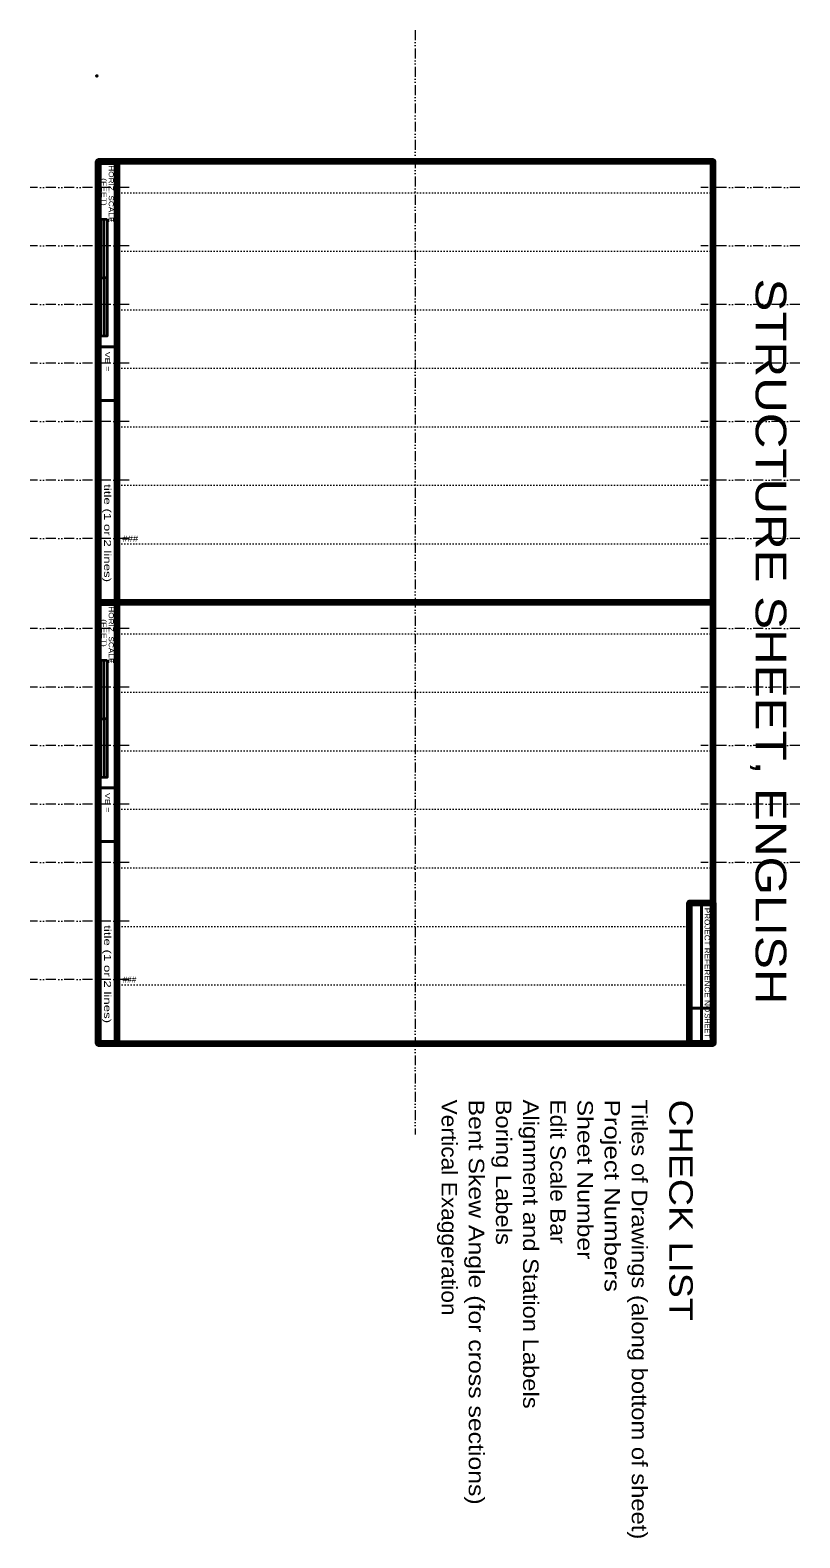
# Model space of a CAD drawing. Extents: x 278712 to 279914, y 171254 to 171792.
# Drawn here: x 279271.5 to 279402.9, y 171276.1 to 171533.7 of the extents above; entities that cross this region are included whole.
import ezdxf
from ezdxf.enums import TextEntityAlignment as Align

# ---------------------------------------------------------------- set-up
doc = ezdxf.new("R2010")
doc.units = 0
doc.header["$LTSCALE"] = 0.34
doc.header["$PDMODE"] = 32
doc.header["$PDSIZE"] = 0.17
doc.linetypes.add('DASH_DOUBLE_DOT', pattern=[9.2, 5, -1.2, 0.3, -1.2, 0.3, -1.2])
doc.linetypes.add('DOTTED', pattern=[1.5, 0.3, -1.2])
for name, color, linetype, lineweight in [('11', 7, 'DOTTED', 13), ('46', 7, 'DASH_DOUBLE_DOT', 13), ('60', 7, 'Continuous', 35)]:
    doc.layers.add(name, color=color, linetype=linetype, lineweight=lineweight)
doc.layers.add('12', color=7, linetype='Continuous')

msp = doc.modelspace()

# ---------------------------------------------------------------- linework, layer by layer
at = {"layer": '11'}
for p, q in [((279388.1234, 171505.949), (279286.3231, 171505.949)), ((279388.1234, 171495.949), (279286.3231, 171495.949)), ((279388.1234, 171485.949), (279286.3231, 171485.949)), ((279388.1234, 171475.949), (279286.3231, 171475.949)), ((279388.1234, 171465.949), (279286.3231, 171465.949)), ((279388.1234, 171455.949), (279286.3231, 171455.949)), ((279388.1234, 171445.949), (279286.3231, 171445.949)), ((279388.1234, 171430.591), (279286.3231, 171430.591)), ((279388.1234, 171420.591), (279286.3231, 171420.591)), ((279388.1234, 171410.591), (279286.3231, 171410.591)), ((279388.1234, 171400.591), (279286.3231, 171400.591)), ((279388.1234, 171390.591), (279286.3231, 171390.591)), ((279384.1234, 171380.591), (279286.3231, 171380.591)), ((279384.1234, 171370.591), (279286.3231, 171370.591))]:
    msp.add_line(p, q, dxfattribs=at)
at = {"layer": '46'}
for p, q in [((279337.2234, 171533.7227), (279337.2234, 171345.0492)), ((279288.4044, 171506.8455), (279271.5091, 171506.8455)), ((279402.9374, 171506.8455), (279386.0421, 171506.8455)), ((279288.4044, 171496.8455), (279271.5091, 171496.8455)), ((279402.9374, 171496.8455), (279386.0421, 171496.8455)), ((279288.4044, 171486.8455), (279271.5091, 171486.8455)), ((279402.9374, 171486.8455), (279386.0421, 171486.8455)), ((279288.4044, 171476.8455), (279271.5091, 171476.8455)), ((279402.9374, 171476.8455), (279386.0421, 171476.8455)), ((279288.4044, 171466.8455), (279271.5091, 171466.8455)), ((279402.9374, 171466.8455), (279386.0421, 171466.8455)), ((279288.4044, 171456.8455), (279271.5091, 171456.8455)), ((279402.9374, 171456.8455), (279386.0421, 171456.8455)), ((279288.4044, 171446.8455), (279271.5091, 171446.8455)), ((279402.9374, 171446.8455), (279386.0421, 171446.8455)), ((279288.4044, 171431.4875), (279271.5091, 171431.4875)), ((279402.9374, 171431.4875), (279386.0421, 171431.4875)), ((279288.4044, 171421.4875), (279271.5091, 171421.4875)), ((279402.9374, 171421.4875), (279386.0421, 171421.4875)), ((279288.4044, 171411.4875), (279271.5091, 171411.4875)), ((279402.9374, 171411.4875), (279386.0421, 171411.4875)), ((279288.4044, 171401.4875), (279271.5091, 171401.4875)), ((279402.9374, 171401.4875), (279386.0421, 171401.4875)), ((279288.4044, 171391.4875), (279271.5091, 171391.4875)), ((279402.9374, 171391.4875), (279386.0421, 171391.4875)), ((279288.4044, 171381.4875), (279271.5091, 171381.4875)), ((279288.4044, 171371.4875), (279271.5091, 171371.4875))]:
    msp.add_line(p, q, dxfattribs=at)
at = {"layer": '60', "lineweight": 40}
for p, q in [((279286.3231, 171479.603), (279283.1231, 171479.6032)), ((279286.3231, 171470.4395), (279283.1231, 171470.4397)), ((279283.1231, 171459.949), (279283.1231, 171435.949)), ((279286.3231, 171404.245), (279283.1231, 171404.245)), ((279286.3231, 171395.0815), (279283.1231, 171395.0815)), ((279283.1231, 171384.591), (279283.1231, 171360.591)), ((279384.1234, 171384.591), (279384.1234, 171360.591)), ((279388.1234, 171384.591), (279384.1234, 171384.591)), ((279386.1234, 171384.591), (279386.1234, 171360.591)), ((279388.1234, 171366.591), (279384.1234, 171366.5912))]:
    msp.add_line(p, q, dxfattribs=at)
at = {"layer": '60', "lineweight": 90}
msp.add_line((279388.1234, 171435.949), (279283.1231, 171435.949), dxfattribs=at)
for points in [[(279286.3234, 171511.307), (279286.3231, 171435.949), (279283.1229, 171435.949), (279283.1231, 171511.307)], [(279283.1231, 171511.307), (279283.1231, 171360.591), (279388.1234, 171360.591), (279388.1234, 171511.307)], [(279286.3234, 171435.949), (279286.3231, 171360.591), (279283.1229, 171360.591), (279283.1231, 171435.949)], [(279388.1234, 171384.591), (279388.1234, 171360.591), (279384.1234, 171360.591), (279384.1234, 171384.591)]]:
    msp.add_lwpolyline(points, close=True, dxfattribs=at)
at = {"layer": '60'}
for points in [[(279284.6371, 171501.4097), (279284.6371, 171481.4097), (279283.6371, 171481.4097), (279283.6371, 171501.4097)], [(279284.6371, 171501.4097), (279284.6371, 171491.4097), (279284.1371, 171491.4097), (279284.1371, 171501.4097)], [(279284.1371, 171491.4097), (279284.1371, 171481.4097), (279283.6371, 171481.4097), (279283.6371, 171491.4097)], [(279284.6371, 171426.0517), (279284.6371, 171406.0517), (279283.6371, 171406.0517), (279283.6371, 171426.0517)], [(279284.6371, 171426.0517), (279284.6371, 171416.0517), (279284.1371, 171416.0517), (279284.1371, 171426.0517)], [(279284.1371, 171416.0517), (279284.1371, 171406.0517), (279283.6371, 171406.0517), (279283.6371, 171416.0517)]]:
    msp.add_lwpolyline(points, close=True, dxfattribs=at)
for p in [(279282.9054, 171525.9155), (279388.3411, 171360.4217)]:
    msp.add_point(p, dxfattribs=at)

# ---------------------------------------------------------------- texts
at = {"layer": '12'}
for width, p in [(1.2, (279288.6041, 171446.3455)), (1.05, (279288.462, 171370.9875))]:
    msp.add_text('###', height=1, dxfattribs=dict(at, width=width)).set_placement(p, align=Align.CENTER)
at = {"layer": '60'}
for s, height, width, p in [('HORIZ. SCALE', 0.84, 1.25, (279284.9231, 171505.7641)), ('(FEET)', 0.84, 1.3, (279283.6831, 171506.0783)), ('0', 0.84, 0.9, (279285.1129, 171501.3732)), ('STRUCTURE SHEET, ENGLISH', 5.25, 1.2, (279395.3851, 171429.2638)), ('title (1 or 2 lines) ', 1.167, 1.45, (279284.1399, 171447.469)), ('HORIZ. SCALE', 0.84, 1.25, (279284.9231, 171430.4062)), ('(FEET)', 0.84, 1.3, (279283.6831, 171430.7203)), ('0', 0.84, 0.9, (279285.1129, 171426.0152)), ('PROJECT REFERENCE NO.', 0.9, 1.15, (279386.6734, 171374.6573)), ('title (1 or 2 lines) ', 1.167, 1.45, (279284.1399, 171372.1107))]:
    msp.add_text(s, height=height, rotation=270, dxfattribs=dict(at, width=width)).set_placement(p, align=Align.CENTER)
for s, height, width, p in [('VE =  ', 0.84, 1.35, (279284.3031, 171478.7572)), ('VE =  ', 0.84, 1.35, (279284.3031, 171403.399)), ('Vertical Exaggeration', 2.64, 1.1, (279341.7626, 171351.0007)), ('Bent Skew Angle (for cross sections)', 2.64, 1.2, (279346.4026, 171351.0007)), ('Boring Labels', 2.64, 1.15, (279351.0426, 171351.0007)), ('Alignment and Station Labels', 2.64, 1.15, (279355.6826, 171351.0007)), ('Edit Scale Bar', 2.64, 1.1, (279360.3226, 171351.0007)), ('Sheet Number', 2.64, 1.2, (279364.9626, 171351.0007)), ('Project Numbers', 2.64, 1.25, (279369.6026, 171351.0007)), ('Titles of Drawings (along bottom of sheet)', 2.64, 1.15, (279374.2426, 171351.0007)), ('CHECK LIST', 4, 1.2, (279380.6429, 171351.0007))]:
    msp.add_text(s, height=height, rotation=270, dxfattribs=dict(at, width=width)).set_placement(p)
msp.add_text('SHEET', height=0.9, rotation=270, dxfattribs=at).set_placement((279386.6734, 171363.6165), align=Align.CENTER)

doc.saveas('drawing.dxf')
